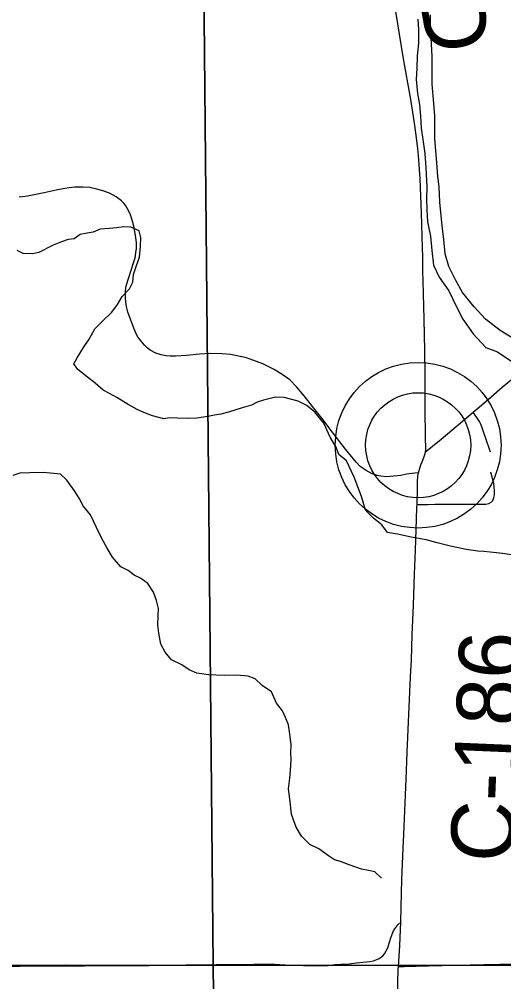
# Model space of a CAD drawing. Extents: x 1985906 to 2360102, y 891258 to 1222054.
# Drawn here: x 2102102 to 2104398, y 1041341 to 1045904 of the extents above; entities that cross this region are included whole.
import ezdxf

# ---------------------------------------------------------------- set-up
doc = ezdxf.new("R2010")
doc.units = 0
for name, color, linetype in [('GM_X_County_Road', 7, 'Continuous'), ('GM_X_County_Road_Text', 7, 'Continuous'), ('GM_X_Major_River', 7, 'Continuous'), ('GM_X_Minor_River', 7, 'Continuous'), ('GM_X_Section', 7, 'Continuous'), ('GM_X_Township_Road', 7, 'Continuous'), ('GM_X_Township_Subdivision', 7, 'Continuous'), ('GM_X_Unincorporated', 7, 'Continuous'), ('GM_X_Unincorporated_Location', 7, 'Continuous')]:
    doc.layers.add(name, color=color, linetype=linetype)

msp = doc.modelspace()

# ---------------------------------------------------------------- linework, layer by layer
at = {"layer": 'GM_X_County_Road'}
for points in [[(2104026.3, 1043851.4), (2104028.7, 1043863.4), (2104028.3, 1043881.5), (2104027.7, 1043908.6), (2104027.4, 1043925), (2104026.6, 1043971), (2104025.8, 1044009.2), (2104025.3, 1044041.4), (2104024.6, 1044075.2), (2104025.8, 1044219.7), (2104023.9, 1044334.7), (2104020.9, 1044482.3), (2104015.2, 1044662.3), (2104014.2, 1044710.6), (2104014, 1044726.6), (2104013.6, 1044774.6), (2104011.2, 1044872.4), (2104008.2, 1044987.3), (2104002.2, 1045148.6), (2103997, 1045216.3), (2103994.1, 1045258.1), (2103991.2, 1045290.2), (2103983.2, 1045354.4), (2103973.6, 1045423), (2103966.9, 1045464.5), (2103957.1, 1045523.7), (2103921.6, 1045726.9), (2103896.4, 1045882.3), (2103872.1, 1046029.1)], [(2103993.3, 1043754.5), (2103976.3, 1043752.2), (2103937.2, 1043747), (2103909.4, 1043741.8), (2103876.4, 1043737.5), (2103842.6, 1043735.7), (2103814.8, 1043737.9), (2103796.7, 1043741.5), (2103789.8, 1043743.8), (2103774.4, 1043750), (2103759.5, 1043757.2), (2103745, 1043765.2), (2103717.4, 1043783.7), (2103697.6, 1043804.4), (2103648.1, 1043866.9), (2103589.9, 1043941.6), (2103535.2, 1044012.8), (2103491, 1044069.3), (2103451.9, 1044118.7), (2103417.2, 1044159.6), (2103383.3, 1044194.3), (2103352.9, 1044216.9), (2103310.4, 1044244.7), (2103256.6, 1044270.7), (2103196.6, 1044293.4), (2103178.2, 1044298.6), (2103127.1, 1044310.5), (2103102.8, 1044314.3), (2103062.9, 1044317.7), (2103007.3, 1044319.4), (2102956.1, 1044316.8), (2102893.6, 1044310.8), (2102842.3, 1044306.4), (2102830.2, 1044306.5), (2102816.4, 1044306.7), (2102798.1, 1044308.2), (2102773.8, 1044314.2), (2102748.6, 1044322.1), (2102722.4, 1044336.2), (2102708.7, 1044346.2), (2102696.7, 1044357.6), (2102685.8, 1044369.7), (2102675.6, 1044382.4), (2102666, 1044395.6), (2102657.5, 1044409.7), (2102644.4, 1044439.8), (2102633.1, 1044470.1), (2102616.4, 1044516.1), (2102613, 1044529.6), (2102609.6, 1044542.8), (2102608, 1044553.1), (2102606.1, 1044565.1), (2102605.3, 1044581.8), (2102604.5, 1044596.5), (2102605.4, 1044616.5), (2102608.9, 1044639.9), (2102621, 1044679.9), (2102642.7, 1044749.3), (2102650.6, 1044773.6), (2102654.9, 1044797.1), (2102656.9, 1044817), (2102656.9, 1044832.7), (2102657, 1044846.7), (2102655, 1044868.4), (2102646.8, 1044916.5), (2102638.9, 1044947.5), (2102628.5, 1044977.6), (2102622.2, 1044992.2), (2102615.3, 1045006.2), (2102607.1, 1045019.5), (2102597.6, 1045031.9), (2102586.7, 1045043.2), (2102574.4, 1045053.1), (2102561.1, 1045061.8), (2102529.9, 1045079.3), (2102498.6, 1045090.6), (2102470, 1045099.3), (2102437, 1045106.2), (2102403.1, 1045108.9), (2102379.7, 1045108.9), (2102365.9, 1045108.1), (2102350.4, 1045107.2), (2102318, 1045102.8), (2102277.2, 1045094.1), (2102219.1, 1045081.1), (2102172.1, 1045071.6), (2102140.9, 1045065.5), (2102117.6, 1045062.4), (2102101.7, 1045061.4)], [(2105354.5, 1044398.9), (2105331, 1044411), (2105305.9, 1044419.7), (2105265.9, 1044427.5), (2105217.3, 1044429.3), (2105171.3, 1044426.7), (2105119.9, 1044420.4), (2105008.4, 1044407.9), (2104960.2, 1044402.4), (2104911.8, 1044396.6), (2104847, 1044388), (2104782.8, 1044376.9), (2104735.4, 1044366), (2104704.4, 1044356.9), (2104674.1, 1044346), (2104644.3, 1044333.8), (2104600.5, 1044312.2), (2104558, 1044288.1), (2104517.1, 1044261.3), (2104478.1, 1044231.8), (2104390.3, 1044158.3), (2104337.5, 1044113)], [(2104337.5, 1044113), (2104280.9, 1044064.3), (2104253.2, 1044040.7)], [(2104253.2, 1044040.7), (2104101.9, 1043912), (2104026.3, 1043851.4)], [(2103993.3, 1043754.5), (2103996.2, 1043765.2), (2104004.8, 1043792.5), (2104010.9, 1043806.9), (2104019.6, 1043826.2), (2104024.2, 1043840.2), (2104026.3, 1043851.4)], [(2103986.8, 1043603.9), (2103988.5, 1043681.8), (2103988.9, 1043702.1), (2103989.6, 1043720.5), (2103990.3, 1043730.5), (2103991.3, 1043739.2), (2103993.3, 1043754.5)], [(2103909.4, 1041624.2), (2103911.5, 1041695.4), (2103914.1, 1041826.7), (2103920.7, 1041974), (2103923.6, 1042039.1), (2103929.2, 1042152.5), (2103934.8, 1042299.7), (2103940.1, 1042429.7), (2103947.2, 1042609.1), (2103956.4, 1042786.7), (2103959.9, 1042867.6), (2103964.2, 1042985.5), (2103969.4, 1043127), (2103974.8, 1043273.7), (2103979.7, 1043387.2), (2103984.7, 1043534.1), (2103986.5, 1043590.8), (2103986.8, 1043603.9)], [(2101987.4, 1041420.1), (2102315.4, 1041421.8), (2102625.4, 1041420.5), (2102890.9, 1041421.6), (2103036.8, 1041422.5), (2103213.8, 1041425.1), (2103263, 1041425.1), (2103312.6, 1041424.2), (2103386, 1041419.8), (2103509.8, 1041416.2), (2103565.5, 1041418.9), (2103599, 1041422.4), (2103626.5, 1041424.2), (2103664.5, 1041426.8), (2103698.9, 1041430.5), (2103763.5, 1041437.4), (2103780.3, 1041440), (2103797.1, 1041446.2), (2103807.6, 1041451.4), (2103824.5, 1041463.9), (2103833.3, 1041474.5), (2103841.3, 1041487.8), (2103848.4, 1041501.9), (2103855.5, 1041524), (2103862.5, 1041548.8), (2103868.7, 1041566.5), (2103875.8, 1041583.3), (2103881.1, 1041592.5), (2103896.3, 1041611.6), (2103909.4, 1041624.2)], [(2103898.9, 1041413.8), (2103902, 1041462.5), (2103904.9, 1041512), (2103907.3, 1041551.8), (2103909.4, 1041624.2)], [(2103894.4, 1041270.9), (2103898.2, 1041402.1), (2103898.9, 1041413.8)]]:
    msp.add_lwpolyline(points, dxfattribs=at)
at = {"layer": 'GM_X_Major_River'}
for points in [[(2103990.8, 1045905.3), (2103993.1, 1045855.3), (2103993.4, 1045791.2), (2103987.8, 1045731.1), (2103986.1, 1045673), (2103982.4, 1045618.9), (2103988.8, 1045552.8), (2103999, 1045500.8), (2104003.4, 1045444.8), (2104005.7, 1045388.7), (2104016, 1045322.7), (2104024.3, 1045268.6), (2104028.7, 1045200.6), (2104033.2, 1045110.5), (2104031.5, 1045054.4), (2104033.8, 1045000.3), (2104036.1, 1044944.2), (2104050.5, 1044876.2), (2104056.8, 1044808.2), (2104065.2, 1044738.1), (2104091.5, 1044682.2), (2104137.9, 1044616.4), (2104172.3, 1044544.5), (2104204.6, 1044482.6), (2104253, 1044412.8), (2104313.3, 1044349), (2104367.5, 1044327.3), (2104435.7, 1044281.6)], [(2104437.1, 1044393.8), (2104380.9, 1044429.5), (2104310.6, 1044483.2), (2104258.3, 1044541), (2104201.9, 1044608.7), (2104169.6, 1044668.6), (2104137.3, 1044732.5), (2104120.9, 1044792.5), (2104114.6, 1044860.6), (2104108.3, 1044912.6), (2104101.9, 1044972.7), (2104095.6, 1045036.7), (2104091.2, 1045108.8), (2104084.9, 1045160.8), (2104078.4, 1045244.9), (2104071.9, 1045337), (2104071.3, 1045447.2), (2104067, 1045505.2), (2104058.5, 1045597.3), (2104058.1, 1045671.4), (2104057.8, 1045727.5), (2104055.5, 1045787.5), (2104051, 1045865.6), (2104050.7, 1045925.7)]]:
    msp.add_lwpolyline(points, dxfattribs=at)
at = {"layer": 'GM_X_Minor_River'}
for points in [[(2104445.8, 1043363.5), (2104391.7, 1043371.3), (2104363.6, 1043375.2), (2104303.4, 1043380.9), (2104275.4, 1043382.8), (2104219.2, 1043390.6), (2104145, 1043406.3), (2104082.8, 1043422.1), (2104030.6, 1043435.9), (2103986.5, 1043443.8), (2103958.4, 1043449.6), (2103894.2, 1043463.4), (2103846.1, 1043471.2), (2103819.8, 1043507.2), (2103781.6, 1043537.2), (2103743.3, 1043577.2), (2103722.9, 1043641.3), (2103706.7, 1043687.4), (2103688.4, 1043733.5), (2103651.9, 1043811.6), (2103615.7, 1043841.6), (2103603.5, 1043875.7), (2103575.2, 1043923.7), (2103544.8, 1043989.8), (2103502.4, 1044041.8), (2103464.2, 1044073.8), (2103424, 1044093.7), (2103357.8, 1044111.4), (2103315.7, 1044113.3), (2103259.7, 1044099), (2103229.7, 1044088.8), (2103201.7, 1044074.6), (2103157.7, 1044062.3), (2103093.6, 1044042), (2103057.6, 1044031.8), (2103027.6, 1044027.6), (2102995.6, 1044021.5), (2102943.5, 1044013.2), (2102901.4, 1044011), (2102851.3, 1044012.8), (2102815.2, 1044014.6), (2102787.2, 1044010.5), (2102733, 1044024.3), (2102692.9, 1044040.2), (2102660.7, 1044054.1), (2102618.5, 1044078), (2102564.2, 1044111.8), (2102530.1, 1044129.8), (2102499.9, 1044145.7), (2102461.7, 1044179.6), (2102425.5, 1044207.6), (2102379.2, 1044243.5), (2102361, 1044271.5), (2102376.9, 1044299.7), (2102406.7, 1044348), (2102432.5, 1044388.3), (2102460.3, 1044436.6), (2102496.2, 1044472.9), (2102540.1, 1044515.3), (2102568, 1044551.5), (2102589.8, 1044589.8), (2102623.7, 1044626.1), (2102639.5, 1044658.3), (2102643.4, 1044694.4), (2102657.2, 1044736.7), (2102671, 1044776.9), (2102676.7, 1044829.1), (2102678.5, 1044869.3), (2102670.3, 1044901.4), (2102630.2, 1044919.2), (2102598.1, 1044921.1), (2102562, 1044914.9), (2102528, 1044912.8), (2102485.9, 1044908.5), (2102451.9, 1044894.3), (2102423.9, 1044890.2), (2102389.9, 1044884), (2102361.9, 1044863.8), (2102333.9, 1044859.7), (2102301.9, 1044849.5), (2102261.9, 1044833.2)], [(2102261.9, 1044833.2), (2102193.9, 1044798.8), (2102165.9, 1044792.7), (2102119.8, 1044794.4), (2102091.7, 1044808.4)], [(2103818.6, 1041834.8), (2103816.6, 1041834.8), (2103786.4, 1041862.8), (2103756.3, 1041868.7), (2103724.2, 1041874.5), (2103666, 1041896.4), (2103623.8, 1041912.2), (2103595.7, 1041920.1), (2103567.5, 1041938.1), (2103521.3, 1041972), (2103479.1, 1041991.9), (2103438.8, 1042031.9), (2103414.5, 1042073.9), (2103402.4, 1042104), (2103392.2, 1042136), (2103383.8, 1042208.3), (2103377.5, 1042256.4), (2103383.3, 1042306.7), (2103387.1, 1042342.8), (2103390.8, 1042395), (2103388.6, 1042427.1), (2103390.4, 1042465.3), (2103386.2, 1042503.4), (2103377.9, 1042559.6), (2103363.7, 1042593.7), (2103349.5, 1042625.7), (2103321.3, 1042661.7), (2103297, 1042715.8), (2103252.7, 1042745.7), (2103220.5, 1042777.7), (2103186.4, 1042789.6), (2103132.2, 1042795.4), (2103072.1, 1042793.1), (2102997.9, 1042796.8), (2102943.8, 1042804.6), (2102907.7, 1042820.5), (2102871.5, 1042844.4), (2102823.2, 1042868.2), (2102793, 1042904.3), (2102772.8, 1042942.3), (2102762.5, 1042994.5), (2102758.3, 1043032.6), (2102760, 1043076.8), (2102761.8, 1043110.9), (2102751.6, 1043149), (2102737.4, 1043189.1), (2102711.1, 1043229.1), (2102676.9, 1043255.1), (2102646.8, 1043269), (2102618.6, 1043290.9), (2102582.5, 1043308.8), (2102544.2, 1043354.8), (2102517.9, 1043396.9), (2102493.6, 1043443), (2102467.3, 1043495), (2102438.9, 1043555.1), (2102404.6, 1043597.1), (2102386.4, 1043633.2), (2102364.2, 1043669.2), (2102327.8, 1043719.3), (2102297.6, 1043747.2), (2102249.5, 1043753), (2102215.4, 1043754.9), (2102151.3, 1043754.6), (2102105.2, 1043752.4), (2102071.2, 1043742.2)]]:
    msp.add_lwpolyline(points, dxfattribs=at)
at = {"layer": 'GM_X_Section'}
for points in [[(2097478.9, 1046742.4), (2102970.3, 1046741.1), (2103020.2, 1041420.1), (2097537, 1041391.5)], [(2102970.3, 1046741.1), (2108623.2, 1046652.5), (2108607.2, 1041541.2), (2108608, 1041419.2), (2103020.2, 1041420.1)], [(2103020.2, 1041420.1), (2103084, 1036099.3), (2097550.9, 1036060.4), (2097537, 1041391.5)], [(2108608, 1041419.2), (2108614.1, 1036304.1), (2103084, 1036099.3), (2103020.2, 1041420.1)]]:
    msp.add_lwpolyline(points, close=True, dxfattribs=at)
at = {"layer": 'GM_X_Township_Road'}
msp.add_lwpolyline([(2103898.9, 1041413.8), (2103925.9, 1041414.1), (2104040.8, 1041416.1), (2104303.3, 1041422.7), (2104533.1, 1041427.8), (2104668.5, 1041428.5)], dxfattribs=at)
at = {"layer": 'GM_X_Township_Subdivision'}
for points in [[(2104334.5, 1043851.5), (2104330.3, 1043866.8), (2104316, 1043907.9), (2104298.7, 1043957.3), (2104293.5, 1043972), (2104287.1, 1043988.3), (2104282.9, 1043997.9), (2104274, 1044012.1), (2104259.9, 1044031.5), (2104253.2, 1044040.7)], [(2103986.8, 1043603.9), (2104001.7, 1043604.1), (2104040.2, 1043604.5), (2104070.5, 1043604.9), (2104092, 1043605.1), (2104121.3, 1043605.4), (2104152, 1043605.7), (2104167.4, 1043605.6), (2104183, 1043605.3), (2104213.3, 1043605.6), (2104248.6, 1043606.3), (2104281, 1043606.1), (2104298.1, 1043606), (2104312.3, 1043605.8), (2104326.4, 1043608.1), (2104338.2, 1043614.5), (2104346.5, 1043623.4), (2104351.2, 1043637), (2104353.6, 1043650.5), (2104354.2, 1043668.2), (2104353, 1043687.7), (2104350.1, 1043704.2), (2104336.5, 1043757.4)]]:
    msp.add_lwpolyline(points, dxfattribs=at)
at = {"layer": 'GM_X_Unincorporated'}
for radius in [392.8, 249]:
    msp.add_circle((2103992.1, 1043884.9), radius, dxfattribs=at)
at = {"layer": 'GM_X_Unincorporated_Location'}
msp.add_line((2103992.1, 1043884.9), (2103992.1, 1043884.9), dxfattribs=at)

# ---------------------------------------------------------------- texts
at = {"layer": 'GM_X_County_Road_Text'}
for s, rotation, p in [('RD', 279.9243, (2103945.5, 1046296.7)), ('C-186', 87.5692, (2104443.1, 1041903.7))]:
    msp.add_text(s, height=300, rotation=rotation, dxfattribs=at).set_placement(p)

doc.saveas('drawing.dxf')
